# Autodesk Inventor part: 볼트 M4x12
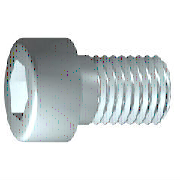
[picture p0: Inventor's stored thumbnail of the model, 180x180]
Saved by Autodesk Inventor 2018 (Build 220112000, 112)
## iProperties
IsCustomPart: 0
Created: 2015-12
Part Number: 볼트 M4x12
Material: 강철, 연강
Description: 6각머리 태핑 나사
Document SubType Name: Modeling
Standard: KS B 1003
Designer: mdu
Standards Organization: KS
Language: ko-KR
Size Designation: M 4 x 12
Categories: <MemberInstance><Categories><Category DisplayName="조임쇠" InternalName="e4da775c-781d-43d5-af7c-5136215cf5a6" Mnemonic="FSTN"><Category DisplayName="볼트" InternalN
Density: 7.86 g/cm^3
Mass: 2.23465 g
Surface Area: 3.30853 cm^2
Volume: 0.284306 cm^3
Appearance: 강철
Author: mdu
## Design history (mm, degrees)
sketch "스케치1"
  geometry: L1 (-1, 0)-(12, 0); L2 (12, 0)-(12, 2); L3 (12, 2)-(1.75, 2); L4 (1.75, 2)-(1.32, 2); L5 (1.32, 2)-(0, 2); L6 (0, 2)-(0, 3.5); L7 (0, 3.5)-(-4, 3.5); L8 (-4, 3.5)-(-4, 1.732); L9 (-4, 1.732)-(-2, 1.732); L10 (-2, 1.732)-(-1, 0); L11 (-7.2, 0)-(15.2, 0) reference; L12 (0, -0.7)-(0, 4.2) reference; L13 (1.75, 2)-(0, 2)
  constraints: 22 end point, 6 parallel, 2 collinear, 2 perpendicular, 1 horizontal, 1 point on line
  dimensions: "d1" = 10.25 distance from line of L3.end L2 (= GEL); "d2" = 0.42952 distance of L4.end L3.end (computed from GAL); "d3" = 4 distance between parallel lines of L8 L6 (= KOH); "d4" = 2 distance of L8.end L9.end (= INTI); "d5" = 60 deg angle of L10 L1; "d6" = 4 diameter of L3 L1 (= GD); "d7" = 4 diameter of L5 L1 (= BDM); "d8" = 3.4641 diameter of L9 L1 (= 1.1547 x SW); "d9" = 7 diameter of L7 L1 (= KOD); "d26" = 12 distance between parallel lines of L12 L2 (= NLG)
revolve "본체" sketch "스케치1" stored, may be unused: angle "d10" = 90 deg
sketch "스케치2"
  geometry: L1 (0, -4.9)-(0, 4.9) reference; L2 (-4.9, 0)-(4.9, 0) reference; L3 (1.732, 0)-(0.866, -1.5); L4 (0.866, -1.5)-(-0.866, -1.5); L5 (-0.866, -1.5)-(-1.732, 0); L6 (-1.732, 0)-(-0.866, 1.5); L7 (-0.866, 1.5)-(0.866, 1.5); L8 (0.866, 1.5)-(1.732, 0); 2 further points
  constraints: 12 end point, 1 coincident, 1 horizontal alignment, 1 point on line, 12 other
extrude "슬롯" join sketch "스케치2" stored distance "d11" = 10; taper "d12" = 0 deg
workplane "Work Plane1"
fillet "Fillet2" dims "d30" = 0.1 (= R)
body "Solid1"
fillet "모깎기1" dims "d17" = 0.4 (= RR)
feature "스레드" dims "d13" = 10.25 (= GEL), "d14" = 0
chamfer "모따기1" distance "d15" = 0.42941 (= -0.5 x SPD + 0.5 x GD); stored, may be unused: second distance "d16" = 0.42941 (= GUL), angle "d27" = 45 deg
other parameters: "GD" = 4 (= NND) [user parameter; used in 2 equation terms], "NLG" = 12 [user parameter; used in 1 equation term], "GEL" = 10.25 [user parameter; used in 2 equation terms], "KOD" = 7 [user parameter; used in 1 equation term], "KOH" = 4 [user parameter; used in 1 equation term], "INTI" = 2 [user parameter; used in 1 equation term], "GAL" = 0.42941 (= 0.61345 x PTC) [user parameter; used in 1 equation term], "GUL" = 0.42941 (= 0.61345 x PTC) [user parameter; used in 1 equation term], "BDM" = 4 (= NND) [user parameter; used in 1 equation term], "SW" = 3 [user parameter; used in 2 equation terms], "RR" = 0.4 [user parameter; used in 1 equation term], "SPD" = 3.14117 (= NND - 1.2269 x PTC) [user parameter; used in 1 equation term], "d19" = 0, "d28" = 0, "d29" = 0, "R" = 0.1 [user parameter; used in 1 equation term], "PHH" = 0.2 [user parameter], "GD1" = 3.14117 (= THREADDIA - 1.2269 x PTC) [user parameter], "THREADDIA" = 4 [user parameter; used in 1 equation term], "FAWI" = 45 deg [user parameter], "TPU" = 14.28571 (computed from PTC) [user parameter], "PTC" = 0.7 [user parameter; used in 5 equation terms], "NND" = 4 [user parameter; used in 3 equation terms], "TOA" = 30 deg [user parameter], "E0" = 3.465 (= 1.155 x SW) [user parameter]
